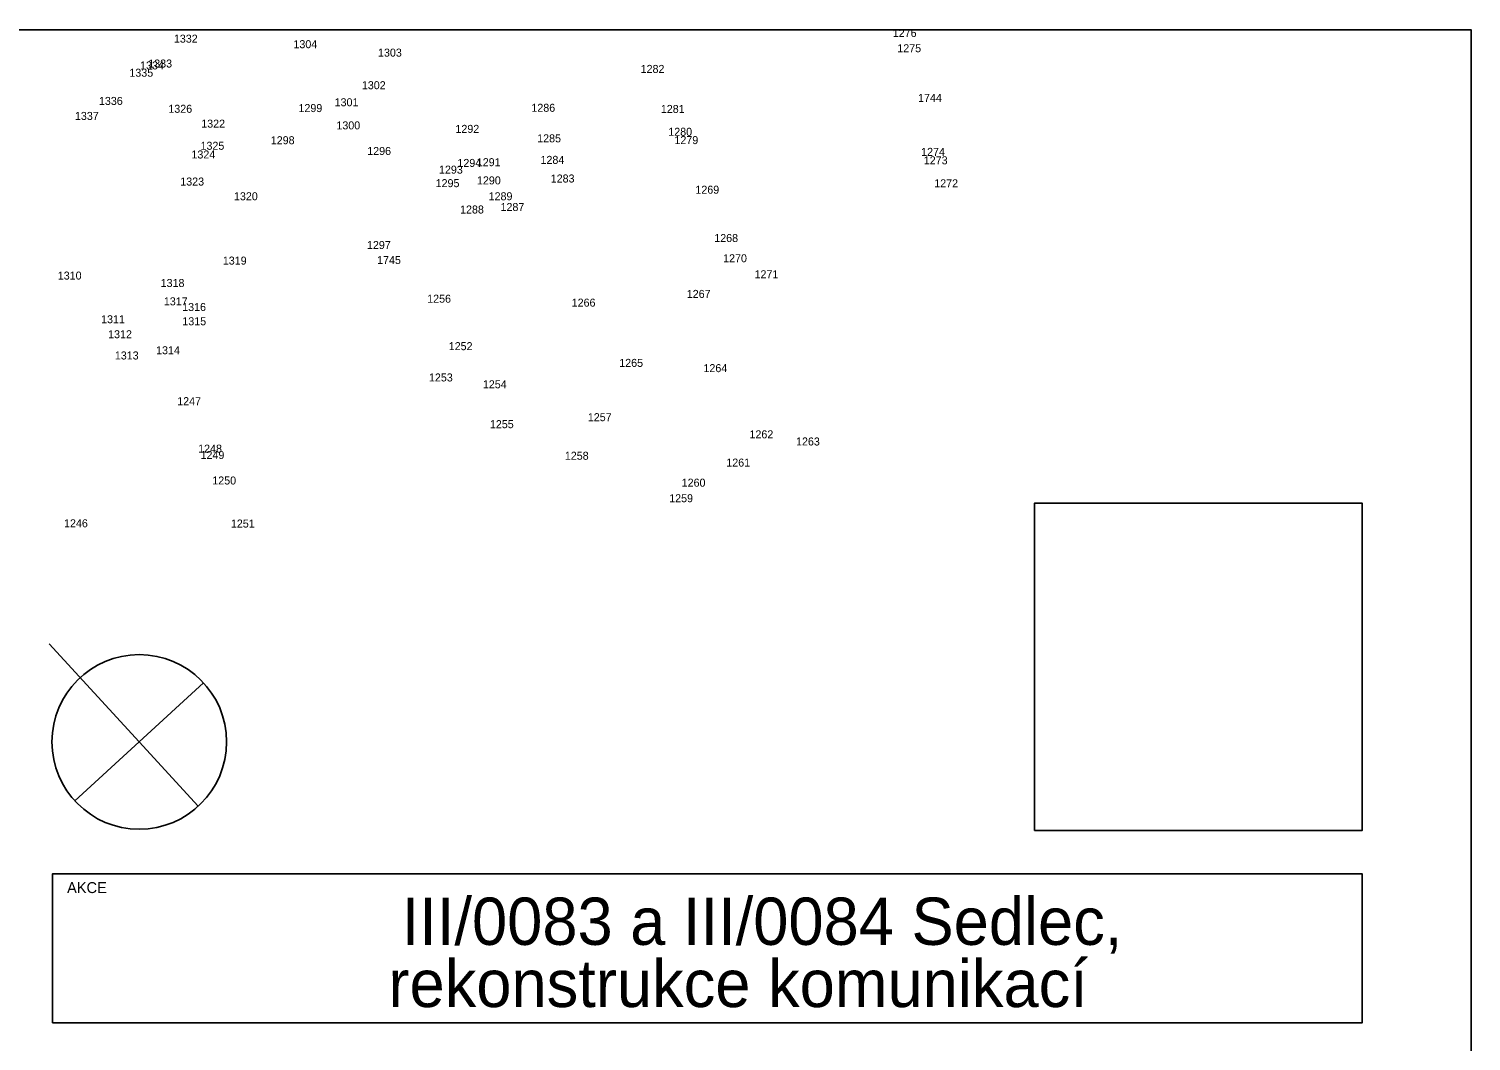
# Model space of a CAD drawing. Extents: x -740053 to -737481, y -1033516 to -1032488.
# Drawn here: x -737581.2 to -737482.1, y -1032876.3 to -1032806.7 of the extents above; entities that cross this region are included whole.
import ezdxf

# ---------------------------------------------------------------- set-up
doc = ezdxf.new("R2010")
doc.units = 0
for name, color, linetype in [('bod-cislo', 7, 'Continuous'), ('Predmety bez rozlišeni', 7, 'Continuous'), ('promika-formát', 7, 'Continuous'), ('promika-rozp', 7, 'Continuous'), ('promika-rozp-poznamky', 7, 'Continuous'), ('promika-rozp-text-firmy', 7, 'Continuous')]:
    doc.layers.add(name, color=color, linetype=linetype)

msp = doc.modelspace()

# ---------------------------------------------------------------- linework, layer by layer
at = {"layer": 'Predmety bez rozlišeni'}
for q in [(-737579.833, -1032848.961), (-737569.221, -1032851.639), (-737578.056, -1032859.76), (-737569.578, -1032860.117)]:
    msp.add_line((-737573.639, -1032855.7), q, dxfattribs=at)
msp.add_circle((-737573.639, -1032855.7), 6, dxfattribs=at)
at = {"layer": 'promika-formát'}
msp.add_lwpolyline([(-737587.097, -1032955.262), (-737482.097, -1032955.262), (-737482.097, -1032806.762), (-737587.097, -1032806.762)], close=True, dxfattribs=at)
at = {"layer": 'promika-rozp'}
msp.add_lwpolyline([(-737579.597, -1032875.012), (-737489.597, -1032875.012), (-737489.597, -1032864.762), (-737579.597, -1032864.762)], close=True, dxfattribs=at)
at = {"layer": 'promika-rozp-poznamky'}
msp.add_lwpolyline([(-737512.097, -1032861.792), (-737489.597, -1032861.792), (-737489.597, -1032839.292), (-737512.097, -1032839.292)], close=True, dxfattribs=at)

# ---------------------------------------------------------------- texts
at = {"layer": 'bod-cislo'}
for s, p in [('1332', (-737571.258, -1032807.653)), ('1304', (-737563.041, -1032808.033)), ('1276', (-737521.848, -1032807.263)), ('1303', (-737557.228, -1032808.613)), ('1275', (-737521.538, -1032808.313)), ('1335', (-737574.318, -1032809.993)), ('1334', (-737573.581, -1032809.493)), ('1333', (-737573.018, -1032809.363)), ('1282', (-737539.178, -1032809.733)), ('1302', (-737558.338, -1032810.853)), ('1336', (-737576.408, -1032811.933)), ('1301', (-737560.21, -1032812.023)), ('1744', (-737520.111, -1032811.723)), ('1337', (-737578.058, -1032812.963)), ('1326', (-737571.638, -1032812.473)), ('1299', (-737562.695, -1032812.423)), ('1286', (-737546.688, -1032812.403)), ('1281', (-737537.79, -1032812.483)), ('1322', (-737569.378, -1032813.493)), ('1300', (-737560.088, -1032813.613)), ('1292', (-737551.908, -1032813.853)), ('1280', (-737537.278, -1032814.053)), ('1325', (-737569.428, -1032815.013)), ('1298', (-737564.598, -1032814.633)), ('1285', (-737546.288, -1032814.503)), ('1279', (-737536.855, -1032814.623)), ('1324', (-737570.051, -1032815.613)), ('1296', (-737557.968, -1032815.373)), ('1284', (-737546.061, -1032815.983)), ('1274', (-737519.901, -1032815.433)), ('1273', (-737519.718, -1032816.013)), ('1293', (-737553.038, -1032816.653)), ('1294', (-737551.771, -1032816.193)), ('1291', (-737550.44, -1032816.143)), ('1323', (-737570.818, -1032817.473)), ('1295', (-737553.268, -1032817.583)), ('1290', (-737550.428, -1032817.393)), ('1283', (-737545.358, -1032817.263)), ('1269', (-737535.415, -1032818.033)), ('1272', (-737518.998, -1032817.593)), ('1320', (-737567.128, -1032818.483)), ('1289', (-737549.625, -1032818.483)), ('1288', (-737551.588, -1032819.393)), ('1287', (-737548.808, -1032819.223)), ('1297', (-737557.988, -1032821.833)), ('1268', (-737534.118, -1032821.353)), ('1319', (-737567.895, -1032822.903)), ('1745', (-737557.291, -1032822.865)), ('1270', (-737533.508, -1032822.743)), ('1310', (-737579.238, -1032823.933)), ('1271', (-737531.35, -1032823.843)), ('1318', (-737572.168, -1032824.443)), ('1317', (-737571.948, -1032825.703)), ('1256', (-737553.848, -1032825.523)), ('1266', (-737543.918, -1032825.793)), ('1267', (-737536.008, -1032825.193)), ('1311', (-737576.26, -1032826.933)), ('1316', (-737570.688, -1032826.093)), ('1312', (-737575.778, -1032827.963)), ('1315', (-737570.678, -1032827.073)), ('1252', (-737552.368, -1032828.783)), ('1313', (-737575.318, -1032829.423)), ('1314', (-737572.481, -1032829.063)), ('1265', (-737540.648, -1032829.933)), ('1253', (-737553.728, -1032830.933)), ('1264', (-737534.861, -1032830.293)), ('1254', (-737550.021, -1032831.403)), ('1247', (-737571.028, -1032832.563)), ('1257', (-737542.808, -1032833.663)), ('1255', (-737549.538, -1032834.143)), ('1262', (-737531.698, -1032834.843)), ('1248', (-737569.588, -1032835.823)), ('1263', (-737528.498, -1032835.333)), ('1249', (-737569.425, -1032836.263)), ('1258', (-737544.388, -1032836.313)), ('1261', (-737533.29, -1032836.783)), ('1250', (-737568.618, -1032838.013)), ('1260', (-737536.358, -1032838.163)), ('1259', (-737537.215, -1032839.233)), ('1246', (-737578.808, -1032840.953)), ('1251', (-737567.34, -1032840.973))]:
    msp.add_text(s, height=0.55, dxfattribs=at).set_placement(p)
at = {"layer": 'promika-rozp'}
msp.add_text('AKCE', height=0.75, dxfattribs=at).set_placement((-737578.599, -1032866.087))
at = {"layer": 'promika-rozp-text-firmy'}
for s, p in [('III/0083 a III/0084 Sedlec,', (-737555.598, -1032869.648)), ('rekonstrukce komunikací', (-737556.509, -1032873.92))]:
    msp.add_text(s, height=3.25, dxfattribs=at).set_placement(p)

doc.saveas('drawing.dxf')
